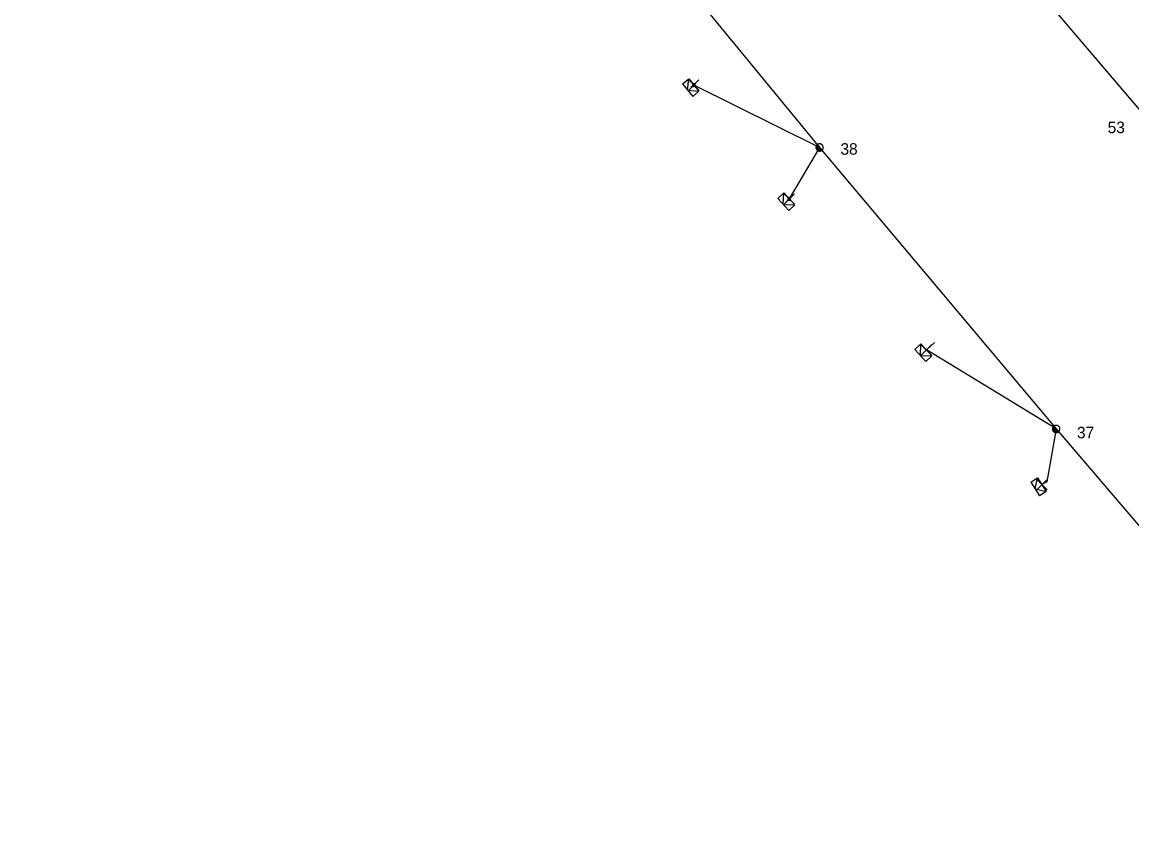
# Model space of a CAD drawing. Extents: x -536148 to -535465, y -1201639 to -1201298.
# Drawn here: x -535704.3 to -535608.3, y -1201492.5 to -1201422.6 of the extents above; entities that cross this region are included whole.
import ezdxf

# ---------------------------------------------------------------- set-up
doc = ezdxf.new("R2010")
doc.units = 0
for name, color, linetype in [('CIZÍ_NADZEM_POPIS', 7, 'Continuous'), ('CIZÍ_PODZEM', 7, 'Continuous'), ('DOPLŇ_POPISY', 7, 'Continuous'), ('ELE_EON', 7, 'Continuous'), ('ELE_EON_POPIS', 7, 'Continuous'), ('KN_VKP_HRAN_NEZNATELNÁ', 7, 'Continuous'), ('KN_VKP_HRAN_SPORNÁ', 7, 'Continuous'), ('PB_NN_POPIS', 7, 'Continuous'), ('PLG_EXPORT_GPE', 7, 'Continuous'), ('PODZEM_NN_POPIS', 7, 'Continuous')]:
    doc.layers.add(name, color=color, linetype=linetype)

# ---------------------------------------------------------------- blocks, each defined once
blk = doc.blocks.new('NN440')
at = {"layer": 'ELE_EON_POPIS'}
for points in [[(0.63, 0), (0.63, 0.06), (0.62, 0.13), (0.6, 0.19), (0.58, 0.25), (0.55, 0.31), (0.51, 0.37), (0.47, 0.42), (0.42, 0.46), (0.37, 0.51), (0.32, 0.54), (0.26, 0.57), (0.2, 0.59), (0.13, 0.61), (0.07, 0.62), (0, 0.63), (-0.06, 0.62), (-0.13, 0.61), (-0.19, 0.59), (-0.26, 0.57), (-0.31, 0.54), (-0.37, 0.51), (-0.42, 0.46), (-0.47, 0.42), (-0.51, 0.37), (-0.54, 0.31), (-0.57, 0.25), (-0.6, 0.19), (-0.62, 0.13), (-0.63, 0.06), (-0.63, 0), (-0.63, -0.07), (-0.62, -0.14), (-0.6, -0.2), (-0.57, -0.26), (-0.54, -0.32), (-0.51, -0.37), (-0.47, -0.43), (-0.42, -0.47), (-0.37, -0.51), (-0.31, -0.55), (-0.26, -0.58), (-0.19, -0.6), (-0.13, -0.62), (-0.06, -0.63), (0, -0.63), (0.07, -0.63), (0.13, -0.62), (0.2, -0.6), (0.26, -0.58), (0.32, -0.55), (0.37, -0.51), (0.42, -0.47), (0.47, -0.43), (0.51, -0.37), (0.55, -0.32), (0.58, -0.26), (0.6, -0.2), (0.62, -0.14), (0.63, -0.07), (0.63, 0)], [(-0.63, 0), (0.63, 0)], [(-0.6, -0.18), (0.57, -0.18)], [(-0.51, -0.32), (0.5, -0.32)], [(-0.37, -0.47), (0.35, -0.47)]]:
    blk.add_lwpolyline(points, dxfattribs=at)
blk = doc.blocks.new('NN800')
at = {"layer": 'ELE_EON'}
for points in [[(-0.442, 0.442), (0.442, -0.442)], [(-0.442, -0.442), (0.442, 0.442)]]:
    blk.add_lwpolyline(points, dxfattribs=at)
blk = doc.blocks.new('NN630')
at = {"layer": 'CIZÍ_PODZEM'}
for points in [[(-0.003, -0.7), (-0.703, 0)], [(-0.703, -0.7), (-0.703, 0), (0.697, 0), (0.697, -0.7)], [(-0.703, -0.7), (0.697, -0.7)], [(-0.003, -0.7), (0.697, 0)]]:
    blk.add_lwpolyline(points, dxfattribs=at)
blk = doc.blocks.new('NN500')
at = {"layer": 'ELE_EON_POPIS'}
for points in [[(0, -0.24), (0.02, -0.23), (0.05, -0.23), (0.07, -0.22), (0.09, -0.22), (0.12, -0.2), (0.14, -0.19), (0.16, -0.18), (0.17, -0.16), (0.19, -0.14), (0.2, -0.12), (0.21, -0.1), (0.22, -0.07), (0.23, -0.05), (0.23, -0.02), (0.23, 0), (0.23, 0.02), (0.23, 0.05), (0.22, 0.07), (0.21, 0.1), (0.2, 0.12), (0.19, 0.14), (0.17, 0.16), (0.16, 0.17), (0.14, 0.19), (0.12, 0.2), (0.09, 0.21), (0.07, 0.22), (0.05, 0.23), (0.02, 0.23), (0, 0.23), (-0.03, 0.23), (-0.05, 0.23), (-0.07, 0.22), (-0.1, 0.21), (-0.12, 0.2), (-0.14, 0.19), (-0.16, 0.17), (-0.18, 0.16), (-0.19, 0.14), (-0.2, 0.12), (-0.22, 0.1), (-0.22, 0.07), (-0.23, 0.05), (-0.23, 0.02), (-0.24, 0), (-0.23, -0.02), (-0.23, -0.05), (-0.22, -0.07), (-0.22, -0.1), (-0.2, -0.12), (-0.19, -0.14), (-0.18, -0.16), (-0.16, -0.18), (-0.14, -0.19), (-0.12, -0.2), (-0.1, -0.22), (-0.07, -0.22), (-0.05, -0.23), (-0.03, -0.23), (0, -0.24)], [(0, -0.24), (0.02, -0.23), (0.05, -0.23), (0.07, -0.22), (0.09, -0.22), (0.12, -0.2), (0.14, -0.19), (0.16, -0.18), (0.17, -0.16), (0.19, -0.14), (0.2, -0.12), (0.21, -0.1), (0.22, -0.07), (0.23, -0.05), (0.23, -0.02), (0.23, 0), (0.23, 0.02), (0.23, 0.05), (0.22, 0.07), (0.21, 0.1), (0.2, 0.12), (0.19, 0.14), (0.17, 0.16), (0.16, 0.17), (0.14, 0.19), (0.12, 0.2), (0.09, 0.21), (0.07, 0.22), (0.05, 0.23), (0.02, 0.23), (0, 0.23), (-0.03, 0.23), (-0.05, 0.23), (-0.07, 0.22), (-0.1, 0.21), (-0.12, 0.2), (-0.14, 0.19), (-0.16, 0.17), (-0.18, 0.16), (-0.19, 0.14), (-0.2, 0.12), (-0.22, 0.1), (-0.22, 0.07), (-0.23, 0.05), (-0.23, 0.02), (-0.24, 0), (-0.23, -0.02), (-0.23, -0.05), (-0.22, -0.07), (-0.22, -0.1), (-0.2, -0.12), (-0.19, -0.14), (-0.18, -0.16), (-0.16, -0.18), (-0.14, -0.19), (-0.12, -0.2), (-0.1, -0.22), (-0.07, -0.22), (-0.05, -0.23), (-0.03, -0.23), (0, -0.24)], [(0, -0.21), (0.02, -0.2), (0.04, -0.2), (0.06, -0.2), (0.08, -0.19), (0.1, -0.18), (0.12, -0.17), (0.14, -0.15), (0.15, -0.14), (0.16, -0.12), (0.18, -0.1), (0.19, -0.08), (0.19, -0.06), (0.2, -0.04), (0.2, -0.02), (0.2, 0), (0.2, 0.02), (0.2, 0.04), (0.19, 0.06), (0.19, 0.08), (0.18, 0.1), (0.16, 0.12), (0.15, 0.14), (0.14, 0.15), (0.12, 0.17), (0.1, 0.18), (0.08, 0.19), (0.06, 0.19), (0.04, 0.2), (0.02, 0.2), (0, 0.2), (-0.02, 0.2), (-0.04, 0.2), (-0.06, 0.19), (-0.08, 0.19), (-0.1, 0.18), (-0.12, 0.17), (-0.14, 0.15), (-0.15, 0.14), (-0.17, 0.12), (-0.18, 0.1), (-0.19, 0.08), (-0.2, 0.06), (-0.2, 0.04), (-0.21, 0.02), (-0.21, 0), (-0.21, -0.02), (-0.2, -0.04), (-0.2, -0.06), (-0.19, -0.08), (-0.18, -0.1), (-0.17, -0.12), (-0.15, -0.14), (-0.14, -0.15), (-0.12, -0.17), (-0.1, -0.18), (-0.08, -0.19), (-0.06, -0.2), (-0.04, -0.2), (-0.02, -0.2), (0, -0.21)], [(0, -0.18), (0.02, -0.18), (0.04, -0.17), (0.05, -0.17), (0.07, -0.16), (0.09, -0.15), (0.1, -0.14), (0.12, -0.13), (0.13, -0.12), (0.14, -0.1), (0.15, -0.09), (0.16, -0.07), (0.17, -0.05), (0.17, -0.04), (0.17, -0.02), (0.17, 0), (0.17, 0.02), (0.17, 0.04), (0.17, 0.05), (0.16, 0.07), (0.15, 0.09), (0.14, 0.1), (0.13, 0.12), (0.12, 0.13), (0.1, 0.14), (0.09, 0.15), (0.07, 0.16), (0.05, 0.17), (0.04, 0.17), (0.02, 0.17), (0, 0.18), (-0.02, 0.17), (-0.04, 0.17), (-0.06, 0.17), (-0.07, 0.16), (-0.09, 0.15), (-0.1, 0.14), (-0.12, 0.13), (-0.13, 0.12), (-0.14, 0.1), (-0.15, 0.09), (-0.16, 0.07), (-0.17, 0.05), (-0.17, 0.04), (-0.18, 0.02), (-0.18, 0), (-0.18, -0.02), (-0.17, -0.04), (-0.17, -0.05), (-0.16, -0.07), (-0.15, -0.09), (-0.14, -0.1), (-0.13, -0.12), (-0.12, -0.13), (-0.1, -0.14), (-0.09, -0.15), (-0.07, -0.16), (-0.06, -0.17), (-0.04, -0.17), (-0.02, -0.18), (0, -0.18)], [(0, -0.15), (0.01, -0.15), (0.03, -0.14), (0.04, -0.14), (0.06, -0.13), (0.07, -0.13), (0.08, -0.12), (0.1, -0.11), (0.11, -0.1), (0.12, -0.09), (0.13, -0.07), (0.13, -0.06), (0.14, -0.05), (0.14, -0.03), (0.14, -0.02), (0.14, 0), (0.14, 0.01), (0.14, 0.03), (0.14, 0.04), (0.13, 0.06), (0.13, 0.07), (0.12, 0.09), (0.11, 0.1), (0.1, 0.11), (0.08, 0.12), (0.07, 0.13), (0.06, 0.13), (0.04, 0.14), (0.03, 0.14), (0.01, 0.14), (0, 0.15), (-0.02, 0.14), (-0.03, 0.14), (-0.05, 0.14), (-0.06, 0.13), (-0.07, 0.13), (-0.09, 0.12), (-0.1, 0.11), (-0.11, 0.1), (-0.12, 0.09), (-0.13, 0.07), (-0.13, 0.06), (-0.14, 0.04), (-0.14, 0.03), (-0.15, 0.01), (-0.15, 0), (-0.15, -0.02), (-0.14, -0.03), (-0.14, -0.05), (-0.13, -0.06), (-0.13, -0.07), (-0.12, -0.09), (-0.11, -0.1), (-0.1, -0.11), (-0.09, -0.12), (-0.07, -0.13), (-0.06, -0.13), (-0.05, -0.14), (-0.03, -0.14), (-0.02, -0.15), (0, -0.15)], [(0, -0.12), (0.01, -0.12), (0.02, -0.11), (0.03, -0.11), (0.05, -0.11), (0.06, -0.1), (0.07, -0.09), (0.08, -0.09), (0.09, -0.08), (0.09, -0.07), (0.1, -0.06), (0.11, -0.05), (0.11, -0.04), (0.11, -0.02), (0.11, -0.01), (0.12, 0), (0.11, 0.01), (0.11, 0.02), (0.11, 0.04), (0.11, 0.05), (0.1, 0.06), (0.09, 0.07), (0.09, 0.08), (0.08, 0.09), (0.07, 0.09), (0.06, 0.1), (0.05, 0.11), (0.03, 0.11), (0.02, 0.11), (0.01, 0.12), (0, 0.12), (-0.01, 0.12), (-0.03, 0.11), (-0.04, 0.11), (-0.05, 0.11), (-0.06, 0.1), (-0.07, 0.09), (-0.08, 0.09), (-0.09, 0.08), (-0.1, 0.07), (-0.1, 0.06), (-0.11, 0.05), (-0.11, 0.04), (-0.12, 0.02), (-0.12, 0.01), (-0.12, 0), (-0.12, -0.01), (-0.12, -0.02), (-0.11, -0.04), (-0.11, -0.05), (-0.1, -0.06), (-0.1, -0.07), (-0.09, -0.08), (-0.08, -0.09), (-0.07, -0.09), (-0.06, -0.1), (-0.05, -0.11), (-0.04, -0.11), (-0.03, -0.11), (-0.01, -0.12), (0, -0.12)], [(0, -0.09), (0.01, -0.09), (0.02, -0.09), (0.03, -0.08), (0.03, -0.08), (0.04, -0.08), (0.05, -0.07), (0.06, -0.07), (0.06, -0.06), (0.07, -0.05), (0.07, -0.04), (0.08, -0.04), (0.08, -0.03), (0.08, -0.02), (0.09, -0.01), (0.09, 0), (0.09, 0.01), (0.08, 0.02), (0.08, 0.03), (0.08, 0.03), (0.07, 0.04), (0.07, 0.05), (0.06, 0.06), (0.06, 0.06), (0.05, 0.07), (0.04, 0.07), (0.03, 0.08), (0.03, 0.08), (0.02, 0.08), (0.01, 0.09), (0, 0.09), (-0.01, 0.09), (-0.02, 0.08), (-0.03, 0.08), (-0.04, 0.08), (-0.04, 0.07), (-0.05, 0.07), (-0.06, 0.06), (-0.07, 0.06), (-0.07, 0.05), (-0.08, 0.04), (-0.08, 0.03), (-0.08, 0.03), (-0.09, 0.02), (-0.09, 0.01), (-0.09, 0), (-0.09, -0.01), (-0.09, -0.02), (-0.08, -0.03), (-0.08, -0.04), (-0.08, -0.04), (-0.07, -0.05), (-0.07, -0.06), (-0.06, -0.07), (-0.05, -0.07), (-0.04, -0.08), (-0.04, -0.08), (-0.03, -0.08), (-0.02, -0.09), (-0.01, -0.09), (0, -0.09)], [(0, -0.06), (0, -0.06), (0.01, -0.06), (0.02, -0.05), (0.02, -0.05), (0.03, -0.05), (0.03, -0.05), (0.04, -0.04), (0.04, -0.04), (0.05, -0.03), (0.05, -0.03), (0.05, -0.02), (0.05, -0.02), (0.05, -0.01), (0.06, -0.01), (0.06, 0), (0.06, 0.01), (0.05, 0.01), (0.05, 0.02), (0.05, 0.02), (0.05, 0.03), (0.05, 0.03), (0.04, 0.04), (0.04, 0.04), (0.03, 0.05), (0.03, 0.05), (0.02, 0.05), (0.02, 0.05), (0.01, 0.06), (0, 0.06), (0, 0.06), (-0.01, 0.06), (-0.01, 0.06), (-0.02, 0.05), (-0.02, 0.05), (-0.03, 0.05), (-0.03, 0.05), (-0.04, 0.04), (-0.04, 0.04), (-0.05, 0.03), (-0.05, 0.03), (-0.05, 0.02), (-0.06, 0.02), (-0.06, 0.01), (-0.06, 0.01), (-0.06, 0), (-0.06, -0.01), (-0.06, -0.01), (-0.06, -0.02), (-0.05, -0.02), (-0.05, -0.03), (-0.05, -0.03), (-0.04, -0.04), (-0.04, -0.04), (-0.03, -0.05), (-0.03, -0.05), (-0.02, -0.05), (-0.02, -0.05), (-0.01, -0.06), (-0.01, -0.06), (0, -0.06)], [(0, -0.03), (0, -0.03), (0, -0.03), (0.01, -0.03), (0.01, -0.03), (0.01, -0.02), (0.02, -0.02), (0.02, -0.02), (0.02, -0.02), (0.02, -0.02), (0.02, -0.01), (0.02, -0.01), (0.03, -0.01), (0.03, -0.01), (0.03, 0), (0.03, 0), (0.03, 0), (0.03, 0.01), (0.03, 0.01), (0.02, 0.01), (0.02, 0.01), (0.02, 0.02), (0.02, 0.02), (0.02, 0.02), (0.02, 0.02), (0.01, 0.02), (0.01, 0.02), (0.01, 0.03), (0, 0.03), (0, 0.03), (0, 0.03), (0, 0.03), (-0.01, 0.03), (-0.01, 0.03), (-0.01, 0.02), (-0.02, 0.02), (-0.02, 0.02), (-0.02, 0.02), (-0.02, 0.02), (-0.02, 0.02), (-0.03, 0.01), (-0.03, 0.01), (-0.03, 0.01), (-0.03, 0.01), (-0.03, 0), (-0.03, 0), (-0.03, 0), (-0.03, -0.01), (-0.03, -0.01), (-0.03, -0.01), (-0.03, -0.01), (-0.02, -0.02), (-0.02, -0.02), (-0.02, -0.02), (-0.02, -0.02), (-0.02, -0.02), (-0.01, -0.03), (-0.01, -0.03), (-0.01, -0.03), (0, -0.03), (0, -0.03)], [(0.23, 0), (0.7, 0)]]:
    blk.add_lwpolyline(points, dxfattribs=at)
blk = doc.blocks.new('NN510')
at = {"layer": 'ELE_EON_POPIS'}
blk.add_lwpolyline([(0.001, 0.002), (0.001, 0.939)], dxfattribs=at)

msp = doc.modelspace()

# ---------------------------------------------------------------- linework, layer by layer
at = {"layer": 'CIZÍ_NADZEM_POPIS'}
msp.add_lwpolyline([(-535635.32, -1201433.41), (-535637.943, -1201437.87)], dxfattribs=at)
at = {"layer": 'ELE_EON'}
for points in [[(-535704.28, -1201335.78), (-535687.29, -1201370.27), (-535663.05, -1201399.63), (-535635.32, -1201433.41), (-535614.862, -1201457.774), (-535589.24, -1201487.744), (-535570.255, -1201520.699), (-535562.055, -1201543.241)], [(-535566.21, -1201489.133), (-535573.362, -1201479.314), (-535581.292, -1201468.256), (-535583.925, -1201464.639), (-535590.303, -1201455.917), (-535602.568, -1201439.045), (-535607.499, -1201430.342), (-535618.17, -1201417.757), (-535627.799, -1201404.564)]]:
    msp.add_lwpolyline(points, dxfattribs=at)
at = {"layer": 'PB_NN_POPIS'}
for points in [[(-535635.32, -1201433.41), (-535646.194, -1201428.014)], [(-535614.862, -1201457.774), (-535626.087, -1201450.934)]]:
    msp.add_lwpolyline(points, dxfattribs=at)
at = {"layer": 'PODZEM_NN_POPIS'}
msp.add_lwpolyline([(-535614.862, -1201457.774), (-535615.666, -1201462.339), (-535616.098, -1201462.586)], dxfattribs=at)

# ---------------------------------------------------------------- block references
at = {"layer": 'DOPLŇ_POPISY'}
for name, p, xscale, yscale, rotation in [('NN500', (-535646.194, -1201428.014), 0.5000000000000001, 0.5, -140.7149999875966), ('NN440', (-535635.32, -1201433.41), 0.49999999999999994, 0.5000000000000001, -49.93583344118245), ('NN500', (-535637.943, -1201437.87), 0.5, 0.5, -137.79200000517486), ('NN440', (-535614.862, -1201457.774), 0.5, 0.5, -49.47215274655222)]:
    msp.add_blockref(name, p, dxfattribs=dict(at, xscale=xscale, yscale=yscale, rotation=rotation))
at = {"layer": 'DOPLŇ_POPISY', "rotation": -47.640091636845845}
msp.add_blockref('NN510', (-535626.088, -1201450.934), dxfattribs=at)
at = {"layer": 'KN_VKP_HRAN_NEZNATELNÁ'}
for p in [(-535646.194, -1201428.014), (-535637.943, -1201437.87), (-535626.087, -1201450.934), (-535616.098, -1201462.586)]:
    msp.add_blockref('NN800', p, dxfattribs=at)
at = {"layer": 'KN_VKP_HRAN_SPORNÁ'}
for p, rotation in [((-535646.194, -1201428.014), -50.7410805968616), ((-535637.943, -1201437.87), -47.81139998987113), ((-535626.087, -1201450.934), -47.63102774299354), ((-535616.098, -1201462.586), -57.30592490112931)]:
    msp.add_blockref('NN630', p, dxfattribs=dict(at, rotation=rotation))

# ---------------------------------------------------------------- texts
at = {"layer": 'PLG_EXPORT_GPE'}
for s, p in [('53', (-535610.41, -1201432.177)), ('38', (-535633.519, -1201434.043)), ('37', (-535613.062, -1201458.585))]:
    msp.add_text(s, height=1, dxfattribs=at).set_placement(p)

doc.saveas('drawing.dxf')
